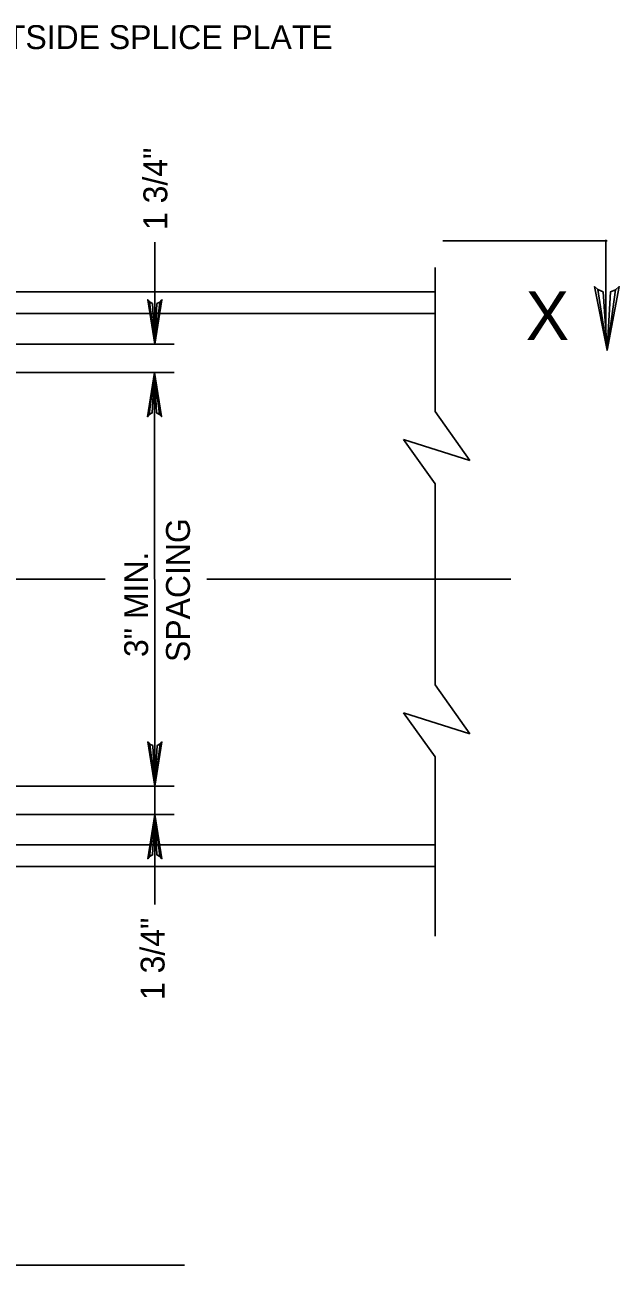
# Model space of a CAD drawing. Extents: x 638466 to 639375, y 297808 to 298996.
# Drawn here: x 638749.4 to 638829.9, y 298104.7 to 298272.9 of the extents above; entities that cross this region are included whole.
import ezdxf

# ---------------------------------------------------------------- set-up
doc = ezdxf.new("R2010")
doc.units = 0
for name, color, linetype in [('1', 7, 'Continuous'), ('2', 7, 'Continuous'), ('4', 7, 'Continuous')]:
    doc.layers.add(name, color=color, linetype=linetype)

msp = doc.modelspace()

# ---------------------------------------------------------------- linework, layer by layer
at = {"layer": '1'}
for points in [[(638827.06, 298237), (638827.77, 298236.7), (638828.3, 298228.77), (638827.06, 298237), (638826.62, 298237.42), (638828.3, 298228.77), (638828.77, 298236.69), (638829.47, 298236.98), (638828.3, 298228.77), (638829.95, 298237.42), (638829.47, 298236.98)], [(638766.27, 298235.33), (638766.68, 298235.11), (638766.98, 298229.6), (638766.27, 298235.33), (638766.02, 298235.62), (638766.98, 298229.6), (638767.26, 298235.11), (638767.67, 298235.31), (638766.98, 298229.6), (638767.94, 298235.62), (638767.67, 298235.31)], [(638766.23, 298220.06), (638766.64, 298220.27), (638766.94, 298225.78), (638766.23, 298220.06), (638765.98, 298219.76), (638766.94, 298225.78), (638767.22, 298220.28), (638767.63, 298220.08), (638766.94, 298225.78), (638767.9, 298219.77), (638767.63, 298220.08)], [(638767.7, 298175.37), (638767.28, 298175.16), (638766.98, 298169.65), (638767.7, 298175.37), (638767.94, 298175.66), (638766.98, 298169.65), (638766.7, 298175.15), (638766.29, 298175.35), (638766.98, 298169.65), (638766.02, 298175.66), (638766.29, 298175.35)], [(638766.27, 298160.1), (638766.68, 298160.32), (638766.98, 298165.82), (638766.27, 298160.1), (638766.02, 298159.81), (638766.98, 298165.82), (638767.26, 298160.32), (638767.67, 298160.12), (638766.98, 298165.82), (638767.94, 298159.81), (638767.67, 298160.12)]]:
    msp.add_lwpolyline(points, dxfattribs=at)
at = {"layer": '2'}
for p, q in [((638804.98, 298240), (638804.98, 298220.45)), ((638608.05, 298236.69), (638804.98, 298236.69)), ((638608.05, 298233.74), (638804.98, 298233.74)), ((638809.7, 298213.81), (638804.98, 298220.45)), ((638804.98, 298210.66), (638800.72, 298216.66)), ((638800.72, 298216.66), (638809.7, 298213.81)), ((638804.98, 298210.66), (638804.98, 298183.4)), ((638809.7, 298176.76), (638804.98, 298183.4)), ((638804.98, 298173.62), (638800.72, 298179.61)), ((638800.72, 298179.61), (638809.7, 298176.76)), ((638804.98, 298149.31), (638804.98, 298173.62)), ((638608.05, 298161.69), (638804.98, 298161.69)), ((638608.05, 298158.73), (638804.98, 298158.73))]:
    msp.add_line(p, q, dxfattribs=at)
at = {"layer": '4'}
for p, q in [((638766.99, 298243.45), (638766.98, 298229.6)), ((638806.05, 298243.61), (638828.3, 298243.61)), ((638828.15, 298231.04), (638828.15, 298243.75)), ((638734.19, 298229.6), (638769.61, 298229.6)), ((638734.19, 298225.78), (638769.61, 298225.78)), ((638766.94, 298225.78), (638766.98, 298169.65)), ((638661.7, 298197.71), (638760.25, 298197.71)), ((638815.24, 298197.71), (638774.04, 298197.71)), ((638734.19, 298169.65), (638769.61, 298169.65)), ((638766.99, 298153.58), (638766.98, 298169.65)), ((638734.19, 298165.82), (638769.61, 298165.82)), ((638770.99, 298104.67), (638643.53, 298104.67))]:
    msp.add_line(p, q, dxfattribs=at)

# ---------------------------------------------------------------- texts
for s, height, p in [('OUTSIDE SPLICE PLATE', 3.2401, (638740.29, 298269.63)), ('X', 6.61, (638817.27, 298230.16))]:
    msp.add_text(s, height=height, dxfattribs=at).set_placement(p)
for s, p in [('1 3/4"', (638768.67, 298245.09)), ('SPACING', (638771.74, 298186.49)), ('3" MIN.', (638766.07, 298187.16)), ('1 3/4"', (638768.3, 298140.64))]:
    msp.add_text(s, height=3.24, rotation=90, dxfattribs=at).set_placement(p)

doc.saveas('drawing.dxf')
